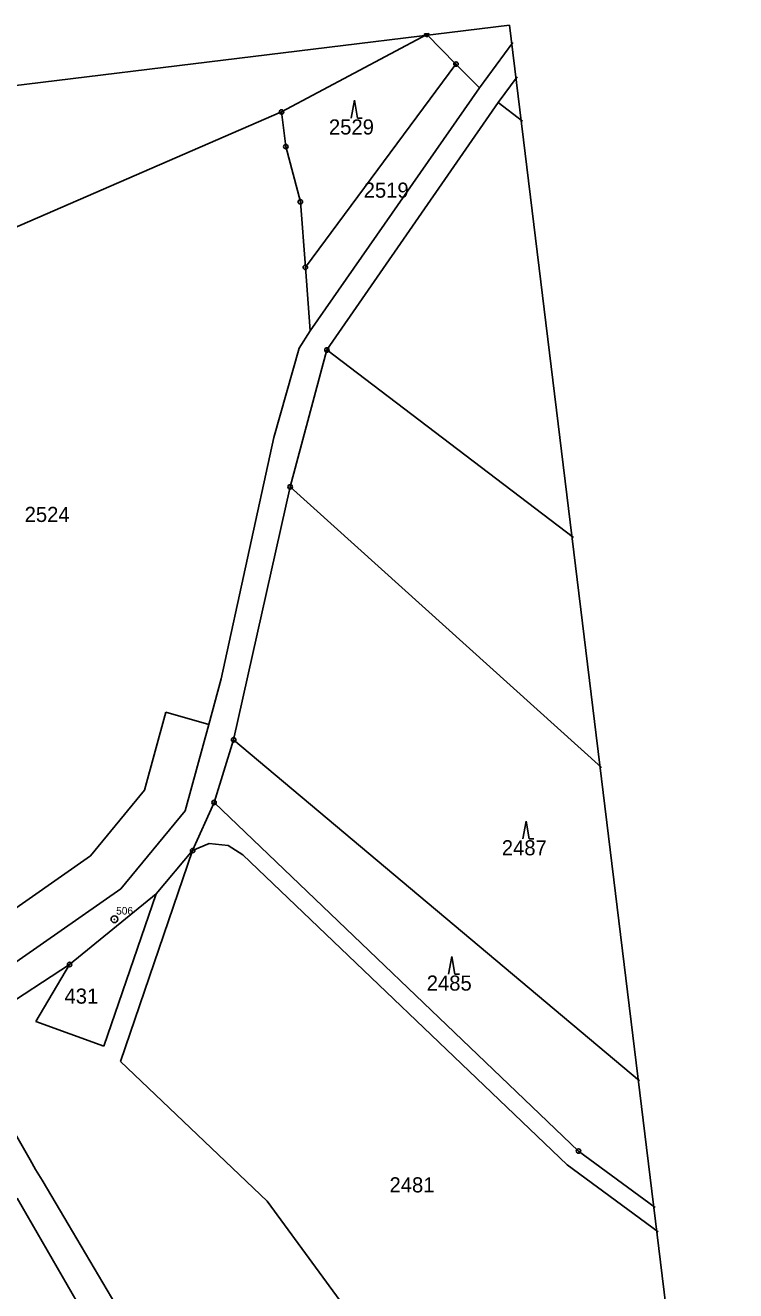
# Model space of a CAD drawing. Extents: x -567356 to -566716, y -1096092 to -1095603.
# Drawn here: x -566875.4 to -566715.7, y -1095888 to -1095603.4 of the extents above; entities that cross this region are included whole.
import ezdxf

# ---------------------------------------------------------------- set-up
doc = ezdxf.new("R2010")
doc.units = 0
for name, color, linetype in [('Vrstva 1', 7, 'Continuous'), ('Vrstva 13', 7, 'Continuous'), ('Vrstva 17', 7, 'Continuous'), ('Vrstva 18', 7, 'Continuous'), ('Vrstva 24', 7, 'Continuous'), ('Vrstva 25', 7, 'Continuous'), ('Vrstva 63', 7, 'Continuous')]:
    doc.layers.add(name, color=color, linetype=linetype)

msp = doc.modelspace()

# ---------------------------------------------------------------- linework, layer by layer
at = {"layer": 'Vrstva 1'}
for p, q in [((-566778.55, -1095612.15), (-566785.11, -1095605.46)), ((-566765.75, -1095607.26), (-566773.29, -1095617.5)), ((-566778.55, -1095612.15), (-566812.41, -1095657.85)), ((-566773.29, -1095617.5), (-566778.55, -1095612.15)), ((-566769.05, -1095620.8), (-566764.8, -1095614.98)), ((-566773.29, -1095617.5), (-566811.32, -1095672.13)), ((-566807.57, -1095676.45), (-566769.05, -1095620.8)), ((-566763.58, -1095625), (-566769.05, -1095620.8)), ((-566817.77, -1095622.91), (-566816.79, -1095630.71)), ((-566816.79, -1095630.71), (-566813.54, -1095643.13)), ((-566813.54, -1095643.13), (-566812.41, -1095657.85)), ((-566812.41, -1095657.85), (-566811.32, -1095672.13)), ((-566811.32, -1095672.13), (-566813.82, -1095676.05)), ((-566813.82, -1095676.05), (-566819.5, -1095696.13)), ((-566815.84, -1095707.24), (-566807.57, -1095676.45)), ((-566807.57, -1095676.45), (-566752.15, -1095718.64)), ((-566819.5, -1095696.13), (-566831.34, -1095750.42)), ((-566828.54, -1095764.12), (-566815.84, -1095707.24)), ((-566745.84, -1095770.35), (-566815.84, -1095707.24)), ((-566831.34, -1095750.42), (-566834.15, -1095760.69)), ((-566848.55, -1095775.42), (-566843.76, -1095757.92)), ((-566843.76, -1095757.92), (-566834.15, -1095760.69)), ((-566834.15, -1095760.69), (-566839.47, -1095780.13)), ((-566832.94, -1095778.22), (-566828.54, -1095764.12)), ((-566828.54, -1095764.12), (-566737.25, -1095840.81)), ((-566860.75, -1095790.2), (-566848.55, -1095775.42)), ((-566837.76, -1095789.04), (-566832.94, -1095778.22)), ((-566751, -1095856.61), (-566832.94, -1095778.22)), ((-566839.47, -1095780.13), (-566853.9, -1095797.61)), ((-566834.04, -1095787.47), (-566837.76, -1095789.04)), ((-566829.74, -1095787.88), (-566834.04, -1095787.47)), ((-566826.45, -1095789.96), (-566829.74, -1095787.88)), ((-566887.09, -1095808.66), (-566860.75, -1095790.2)), ((-566854, -1095836.49), (-566837.76, -1095789.04)), ((-566845.99, -1095798.76), (-566837.76, -1095789.04)), ((-566753.58, -1095859.68), (-566826.45, -1095789.96)), ((-566853.9, -1095797.61), (-566880.71, -1095816.4)), ((-566865.42, -1095814.66), (-566845.99, -1095798.76)), ((-566857.74, -1095833.03), (-566845.99, -1095798.76)), ((-566885.55, -1095827.69), (-566865.42, -1095814.66)), ((-566873.05, -1095827.49), (-566865.42, -1095814.66)), ((-566873.05, -1095827.49), (-566857.74, -1095833.03)), ((-566889.02, -1095832.89), (-566874.28, -1095858.61)), ((-566854, -1095836.49), (-566821.02, -1095867.86)), ((-566874.28, -1095858.61), (-566873.06, -1095860.74)), ((-566751, -1095856.61), (-566733.77, -1095869.31)), ((-566873.06, -1095860.74), (-566871.61, -1095863.18)), ((-566753.58, -1095859.68), (-566733.1, -1095874.79)), ((-566871.61, -1095863.18), (-566837.41, -1095920.88)), ((-566877.22, -1095867.21), (-566842.91, -1095926.64)), ((-566821.02, -1095867.86), (-566759.5, -1095951.78))]:
    msp.add_line(p, q, dxfattribs=at)
at = {"layer": 'Vrstva 13'}
for p, q in [((-566817.77, -1095622.91), (-566785.11, -1095605.46)), ((-566785.11, -1095605.46), (-566785.02, -1095605.3)), ((-566905.05, -1095660.75), (-566817.77, -1095622.91))]:
    msp.add_line(p, q, dxfattribs=at)
at = {"layer": 'Vrstva 24'}
msp.add_lwpolyline([(-566784.65, -1095605.25), (-566785.6, -1095605.37)], dxfattribs=at)
for centre, radius in [((-566785.11, -1095605.46), 0.0327), ((-566778.55, -1095612.15), 0.5), ((-566778.55, -1095612.15), 0.0327), ((-566817.77, -1095622.91), 0.5), ((-566817.77, -1095622.91), 0.0327), ((-566816.79, -1095630.71), 0.5), ((-566816.79, -1095630.71), 0.0327), ((-566813.54, -1095643.13), 0.5), ((-566813.54, -1095643.13), 0.0327), ((-566812.41, -1095657.85), 0.5), ((-566812.41, -1095657.85), 0.0327), ((-566807.57, -1095676.45), 0.5), ((-566807.57, -1095676.45), 0.0327), ((-566815.84, -1095707.24), 0.5), ((-566815.84, -1095707.24), 0.0327), ((-566828.54, -1095764.12), 0.5), ((-566828.54, -1095764.12), 0.0327), ((-566832.94, -1095778.22), 0.5), ((-566832.94, -1095778.22), 0.0327), ((-566837.76, -1095789.04), 0.5), ((-566837.76, -1095789.04), 0.5), ((-566837.76, -1095789.04), 0.0327), ((-566837.76, -1095789.04), 0.0327), ((-566855.35, -1095804.48), 0.75), ((-566855.35, -1095804.48), 0.0327), ((-566865.42, -1095814.66), 0.5), ((-566865.42, -1095814.66), 0.5), ((-566865.42, -1095814.66), 0.0327), ((-566865.42, -1095814.66), 0.0327), ((-566751, -1095856.61), 0.5), ((-566751, -1095856.61), 0.0327)]:
    msp.add_circle(centre, radius, dxfattribs=at)
msp.add_arc((-566785.11, -1095605.46), 0.5, 169.4732, 24.4417, dxfattribs=at)
at = {"layer": 'Vrstva 25'}
for p, q in [((-566801.4, -1095620.28), (-566802.14, -1095624.28)), ((-566801.4, -1095620.28), (-566800.67, -1095624.28)), ((-566800.67, -1095624.28), (-566799.67, -1095624.28)), ((-566762.79, -1095782.39), (-566763.53, -1095786.39)), ((-566762.79, -1095782.39), (-566762.06, -1095786.39)), ((-566762.06, -1095786.39), (-566761.06, -1095786.39)), ((-566779.5, -1095812.82), (-566780.23, -1095816.82)), ((-566779.5, -1095812.82), (-566778.77, -1095816.82)), ((-566778.77, -1095816.82), (-566777.77, -1095816.82))]:
    msp.add_line(p, q, dxfattribs=at)
at = {"layer": 'Vrstva 63'}
for p, q in [((-567356.16, -1095675.38), (-566766.53, -1095603.43)), ((-566766.53, -1095603.43), (-566715.66, -1096020.34))]:
    msp.add_line(p, q, dxfattribs=at)

# ---------------------------------------------------------------- texts
at = {"layer": 'Vrstva 17'}
msp.add_text('506', height=1.7, dxfattribs=at).set_placement((-566854.95, -1095803.42))
at = {"layer": 'Vrstva 18'}
for s, p in [('2529', (-566807.11, -1095627.99)), ('2519', (-566799.3, -1095642.2)), ('2524', (-566875.53, -1095715.13)), ('2487', (-566768.24, -1095790.1)), ('2485', (-566785.12, -1095820.53)), ('431', (-566866.57, -1095823.46)), ('2481', (-566793.49, -1095865.91))]:
    msp.add_text(s, height=3.4, dxfattribs=at).set_placement(p)

doc.saveas('drawing.dxf')
